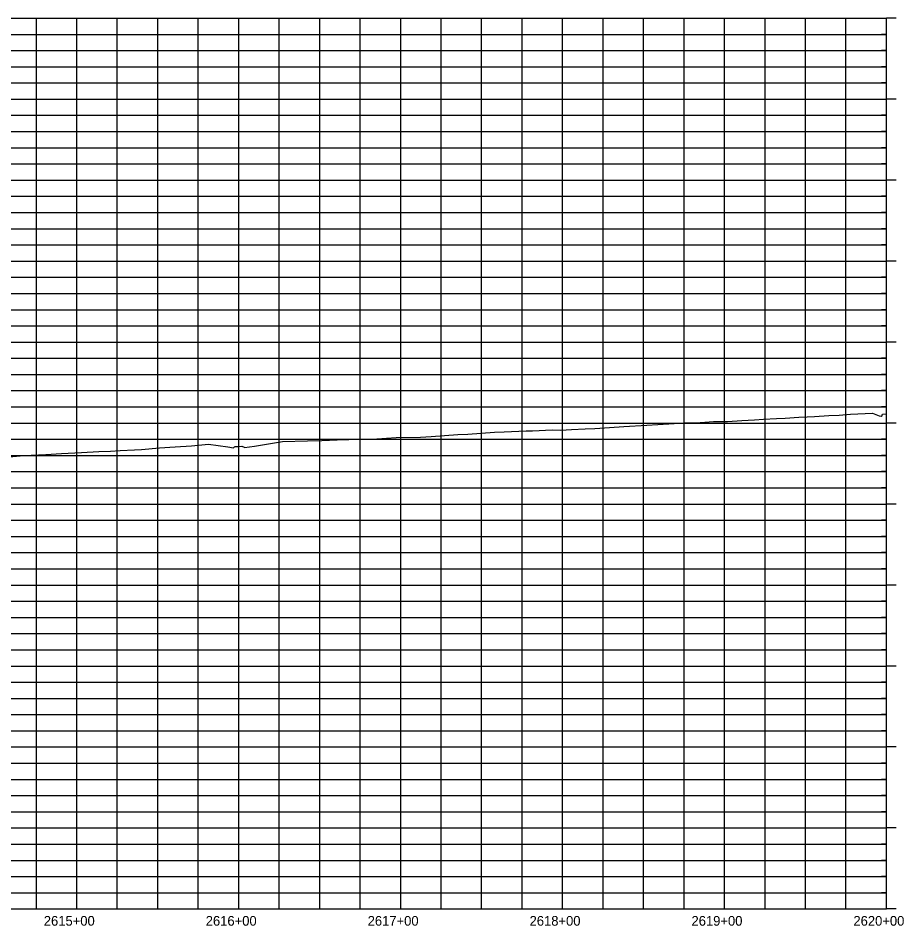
# Model space of a CAD drawing. Extents: x 921603 to 924670, y 1759276 to 1766491.
# Drawn here: x 922604 to 923151, y 1765922 to 1766482 of the extents above; entities that cross this region are included whole.
import ezdxf

# ---------------------------------------------------------------- set-up
doc = ezdxf.new("R2010")
doc.units = 0
for name, color, linetype in [('R_Axis_Annotation', 7, 'Continuous'), ('R_Exist Surface', 7, 'Continuous'), ('R_Grid', 7, 'Continuous'), ('R_Grid Annot', 7, 'Continuous'), ('R_Grid_Minor', 7, 'Continuous')]:
    doc.layers.add(name, color=color, linetype=linetype)

msp = doc.modelspace()

# ---------------------------------------------------------------- linework, layer by layer
at = {"layer": 'R_Exist Surface'}
msp.add_lwpolyline([(922597.98, 1766211.4), (922607.18, 1766212.19), (922620.65, 1766212.82), (922630.33, 1766213.4), (922642.78, 1766214), (922653.45, 1766214.63), (922660.55, 1766214.94), (922666.61, 1766215.27), (922675.35, 1766215.63), (922679.66, 1766215.86), (922690.97, 1766216.93), (922700.46, 1766217.58), (922710.58, 1766218.28), (922721.17, 1766219.2), (922733.09, 1766217.54), (922736.59, 1766217.04), (922737.17, 1766217.49), (922737.66, 1766217.81), (922739.68, 1766217.79), (922741.72, 1766218.07), (922743.06, 1766217.36), (922743.33, 1766217.16), (922749.44, 1766218.06), (922766.87, 1766220.87), (922782.25, 1766221.29), (922791.08, 1766221.56), (922800.67, 1766221.85), (922815.3, 1766222.25), (922825.1, 1766222.52), (922836.94, 1766223.33), (922851.99, 1766223.64), (922858.66, 1766224.03), (922875.06, 1766225.2), (922881.2, 1766225.43), (922897.71, 1766226.59), (922903.73, 1766226.83), (922917.27, 1766227.52), (922921.3, 1766227.52), (922933.41, 1766228.15), (922938.83, 1766227.96), (922945.3, 1766228.19), (922953.77, 1766228.74), (922959.75, 1766228.96), (922968.71, 1766229.54), (922977.56, 1766230.12), (922991.88, 1766230.94), (923005.49, 1766231.72), (923015.02, 1766232.33), (923022.09, 1766232.42), (923032.94, 1766233.18), (923041.7, 1766233.23), (923050.6, 1766233.81), (923058.31, 1766234.29), (923063.96, 1766234.57), (923072.01, 1766235.07), (923077.36, 1766235.35), (923085.71, 1766235.86), (923090.79, 1766236.12), (923095.4, 1766236.36), (923104.25, 1766236.91), (923110.59, 1766237.23), (923117.71, 1766237.67), (923126.6, 1766238.07), (923131.15, 1766238.36), (923135.3, 1766236.81), (923136.77, 1766236.5), (923136.88, 1766236.5), (923137.42, 1766237.83), (923139.76, 1766237.94), (923139.83, 1766237.95)], dxfattribs=at)
at = {"layer": 'R_Grid'}
for p, q in [((921639.83, 1766482.26), (923139.83, 1766482.26)), ((921639.83, 1766482.26), (923139.83, 1766482.26)), ((922639.83, 1765932.26), (922639.83, 1766482.26)), ((922739.83, 1765932.26), (922739.83, 1766482.26)), ((922839.83, 1765932.26), (922839.83, 1766482.26)), ((922939.83, 1765932.26), (922939.83, 1766482.26)), ((923039.83, 1765932.26), (923039.83, 1766482.26)), ((923139.83, 1765932.26), (923139.83, 1766482.26)), ((921639.83, 1766432.26), (923139.83, 1766432.26)), ((921639.83, 1766382.26), (923139.83, 1766382.26)), ((921639.83, 1766332.26), (923139.83, 1766332.26)), ((921639.83, 1766282.26), (923139.83, 1766282.26)), ((921639.83, 1766232.26), (923139.83, 1766232.26)), ((921639.83, 1766182.26), (923139.83, 1766182.26)), ((921639.83, 1766132.26), (923139.83, 1766132.26)), ((921639.83, 1766082.26), (923139.83, 1766082.26)), ((921639.83, 1766032.26), (923139.83, 1766032.26)), ((921639.83, 1765982.26), (923139.83, 1765982.26)), ((921639.83, 1765932.26), (923139.83, 1765932.26))]:
    msp.add_line(p, q, dxfattribs=at)
at = {"layer": 'R_Grid Annot'}
for p, q in [((923145.83, 1766482.26), (923139.83, 1766482.26)), ((923145.83, 1766482.26), (923139.83, 1766482.26)), ((923139.83, 1766472.26), (923136.83, 1766472.26)), ((923139.83, 1766462.26), (923136.83, 1766462.26)), ((923139.83, 1766452.26), (923136.83, 1766452.26)), ((923139.83, 1766442.26), (923136.83, 1766442.26)), ((923145.83, 1766432.26), (923139.83, 1766432.26)), ((923139.83, 1766422.26), (923136.83, 1766422.26)), ((923139.83, 1766412.26), (923136.83, 1766412.26)), ((923139.83, 1766402.26), (923136.83, 1766402.26)), ((923139.83, 1766392.26), (923136.83, 1766392.26)), ((923145.83, 1766382.26), (923139.83, 1766382.26)), ((923139.83, 1766372.26), (923136.83, 1766372.26)), ((923139.83, 1766362.26), (923136.83, 1766362.26)), ((923139.83, 1766352.26), (923136.83, 1766352.26)), ((923139.83, 1766342.26), (923136.83, 1766342.26)), ((923145.83, 1766332.26), (923139.83, 1766332.26)), ((923139.83, 1766322.26), (923136.83, 1766322.26)), ((923139.83, 1766312.26), (923136.83, 1766312.26)), ((923139.83, 1766302.26), (923136.83, 1766302.26)), ((923139.83, 1766292.26), (923136.83, 1766292.26)), ((923145.83, 1766282.26), (923139.83, 1766282.26)), ((923139.83, 1766272.26), (923136.83, 1766272.26)), ((923139.83, 1766262.26), (923136.83, 1766262.26)), ((923139.83, 1766252.26), (923136.83, 1766252.26)), ((923139.83, 1766242.26), (923136.83, 1766242.26)), ((923145.83, 1766232.26), (923139.83, 1766232.26)), ((923139.83, 1766222.26), (923136.83, 1766222.26)), ((923139.83, 1766212.26), (923136.83, 1766212.26)), ((923139.83, 1766202.26), (923136.83, 1766202.26)), ((923139.83, 1766192.26), (923136.83, 1766192.26)), ((923145.83, 1766182.26), (923139.83, 1766182.26)), ((923139.83, 1766172.26), (923136.83, 1766172.26)), ((923139.83, 1766162.26), (923136.83, 1766162.26)), ((923139.83, 1766152.26), (923136.83, 1766152.26)), ((923139.83, 1766142.26), (923136.83, 1766142.26)), ((923145.83, 1766132.26), (923139.83, 1766132.26)), ((923139.83, 1766122.26), (923136.83, 1766122.26)), ((923139.83, 1766112.26), (923136.83, 1766112.26)), ((923139.83, 1766102.26), (923136.83, 1766102.26)), ((923139.83, 1766092.26), (923136.83, 1766092.26)), ((923145.83, 1766082.26), (923139.83, 1766082.26)), ((923139.83, 1766072.26), (923136.83, 1766072.26)), ((923139.83, 1766062.26), (923136.83, 1766062.26)), ((923139.83, 1766052.26), (923136.83, 1766052.26)), ((923139.83, 1766042.26), (923136.83, 1766042.26)), ((923145.83, 1766032.26), (923139.83, 1766032.26)), ((923139.83, 1766022.26), (923136.83, 1766022.26)), ((923139.83, 1766012.26), (923136.83, 1766012.26)), ((923139.83, 1766002.26), (923136.83, 1766002.26)), ((923139.83, 1765992.26), (923136.83, 1765992.26)), ((923145.83, 1765982.26), (923139.83, 1765982.26)), ((923139.83, 1765972.26), (923136.83, 1765972.26)), ((923139.83, 1765962.26), (923136.83, 1765962.26)), ((923139.83, 1765952.26), (923136.83, 1765952.26)), ((923139.83, 1765942.26), (923136.83, 1765942.26)), ((923145.83, 1765932.26), (923139.83, 1765932.26))]:
    msp.add_line(p, q, dxfattribs=at)
at = {"layer": 'R_Grid_Minor'}
for p, q in [((922614.83, 1765932.26), (922614.83, 1766482.26)), ((922664.83, 1765932.26), (922664.83, 1766482.26)), ((922689.83, 1765932.26), (922689.83, 1766482.26)), ((922714.83, 1765932.26), (922714.83, 1766482.26)), ((922764.83, 1765932.26), (922764.83, 1766482.26)), ((922789.83, 1765932.26), (922789.83, 1766482.26)), ((922814.83, 1765932.26), (922814.83, 1766482.26)), ((922864.83, 1765932.26), (922864.83, 1766482.26)), ((922889.83, 1765932.26), (922889.83, 1766482.26)), ((922914.83, 1765932.26), (922914.83, 1766482.26)), ((922964.83, 1765932.26), (922964.83, 1766482.26)), ((922989.83, 1765932.26), (922989.83, 1766482.26)), ((923014.83, 1765932.26), (923014.83, 1766482.26)), ((923064.83, 1765932.26), (923064.83, 1766482.26)), ((923089.83, 1765932.26), (923089.83, 1766482.26)), ((923114.83, 1765932.26), (923114.83, 1766482.26)), ((921639.83, 1766472.26), (923139.83, 1766472.26)), ((921639.83, 1766462.26), (923139.83, 1766462.26)), ((921639.83, 1766452.26), (923139.83, 1766452.26)), ((921639.83, 1766442.26), (923139.83, 1766442.26)), ((921639.83, 1766422.26), (923139.83, 1766422.26)), ((921639.83, 1766412.26), (923139.83, 1766412.26)), ((921639.83, 1766402.26), (923139.83, 1766402.26)), ((921639.83, 1766392.26), (923139.83, 1766392.26)), ((921639.83, 1766372.26), (923139.83, 1766372.26)), ((921639.83, 1766362.26), (923139.83, 1766362.26)), ((921639.83, 1766352.26), (923139.83, 1766352.26)), ((921639.83, 1766342.26), (923139.83, 1766342.26)), ((921639.83, 1766322.26), (923139.83, 1766322.26)), ((921639.83, 1766312.26), (923139.83, 1766312.26)), ((921639.83, 1766302.26), (923139.83, 1766302.26)), ((921639.83, 1766292.26), (923139.83, 1766292.26)), ((921639.83, 1766272.26), (923139.83, 1766272.26)), ((921639.83, 1766262.26), (923139.83, 1766262.26)), ((921639.83, 1766252.26), (923139.83, 1766252.26)), ((921639.83, 1766242.26), (923139.83, 1766242.26)), ((921639.83, 1766222.26), (923139.83, 1766222.26)), ((921639.83, 1766212.26), (923139.83, 1766212.26)), ((921639.83, 1766202.26), (923139.83, 1766202.26)), ((921639.83, 1766192.26), (923139.83, 1766192.26)), ((921639.83, 1766172.26), (923139.83, 1766172.26)), ((921639.83, 1766162.26), (923139.83, 1766162.26)), ((921639.83, 1766152.26), (923139.83, 1766152.26)), ((921639.83, 1766142.26), (923139.83, 1766142.26)), ((921639.83, 1766122.26), (923139.83, 1766122.26)), ((921639.83, 1766112.26), (923139.83, 1766112.26)), ((921639.83, 1766102.26), (923139.83, 1766102.26)), ((921639.83, 1766092.26), (923139.83, 1766092.26)), ((921639.83, 1766072.26), (923139.83, 1766072.26)), ((921639.83, 1766062.26), (923139.83, 1766062.26)), ((921639.83, 1766052.26), (923139.83, 1766052.26)), ((921639.83, 1766042.26), (923139.83, 1766042.26)), ((921639.83, 1766022.26), (923139.83, 1766022.26)), ((921639.83, 1766012.26), (923139.83, 1766012.26)), ((921639.83, 1766002.26), (923139.83, 1766002.26)), ((921639.83, 1765992.26), (923139.83, 1765992.26)), ((921639.83, 1765972.26), (923139.83, 1765972.26)), ((921639.83, 1765962.26), (923139.83, 1765962.26)), ((921639.83, 1765952.26), (923139.83, 1765952.26)), ((921639.83, 1765942.26), (923139.83, 1765942.26))]:
    msp.add_line(p, q, dxfattribs=at)

# ---------------------------------------------------------------- texts
at = {"layer": 'R_Axis_Annotation'}
for s, p in [('2615+00', (922619.42, 1765921.91)), ('2616+00', (922719.42, 1765921.91)), ('2617+00', (922819.42, 1765921.91)), ('2618+00', (922919.42, 1765921.91)), ('2619+00', (923019.42, 1765921.91)), ('2620+00', (923119.42, 1765921.91))]:
    msp.add_text(s, height=6, dxfattribs=at).set_placement(p)

doc.saveas('drawing.dxf')
